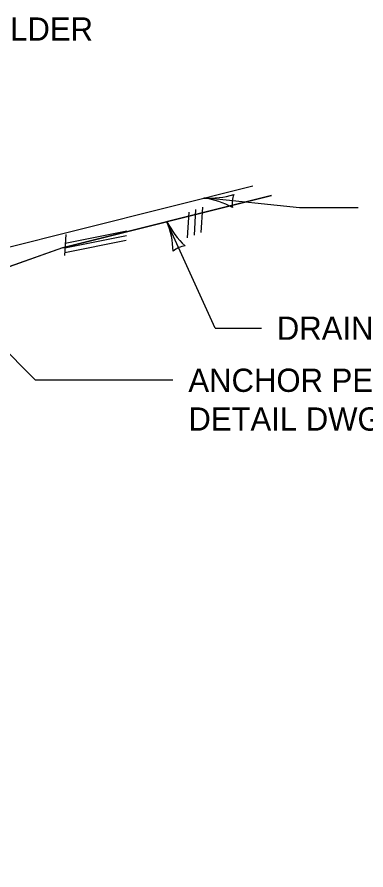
# Model space of a CAD drawing. Extents: x 49991.4 to 50021, y 49987.6 to 50011.4.
# Drawn here: x 50006.177 to 50007.078, y 49991.174 to 49993.376 of the extents above; entities that cross this region are included whole.
import ezdxf

# ---------------------------------------------------------------- set-up
doc = ezdxf.new("R2010")
doc.units = 0
for name, color, linetype in [('Level 1', 7, 'Continuous'), ('Level 2', 7, 'Continuous'), ('Level 3', 7, 'Continuous'), ('Level 4', 7, 'Continuous')]:
    doc.layers.add(name, color=color, linetype=linetype)

msp = doc.modelspace()

# ---------------------------------------------------------------- linework, layer by layer
at = {"layer": 'Level 1'}
for p, q in [((50006.1193, 49992.7741), (50006.7861, 49992.9408)), ((50006.6379, 49992.8791), (50006.6338, 49992.813)), ((50006.6554, 49992.8852), (50006.6513, 49992.82)), ((50006.6205, 49992.8726), (50006.6164, 49992.8065)), ((50006.3026, 49992.8153), (50006.2992, 49992.7609)), ((50006.3005, 49992.7807), (50006.4591, 49992.8126)), ((50006.3012, 49992.7927), (50006.46, 49992.8247)), ((50006.2997, 49992.7682), (50006.4584, 49992.8002))]:
    msp.add_line(p, q, dxfattribs=at)
msp.add_lwpolyline([(50006.8341, 49992.9155), (50006.2939, 49992.7804), (50006.1193, 49992.7186), (50006.0287, 49992.663), (50005.1465, 49992.663), (50002.1692, 49991.1744), (50001.4905, 49991.2052)], dxfattribs=at)
at = {"layer": 'Level 3'}
for p, q in [((50006.9067, 49992.8838), (50006.6595, 49992.9092)), ((50007.0578, 49992.8838), (50006.9067, 49992.8838)), ((50006.6882, 49992.573), (50006.564, 49992.8479)), ((50006.0677, 49992.5963), (50006.2243, 49992.4386)), ((50006.6882, 49992.573), (50006.8078, 49992.573)), ((50006.5793, 49992.4386), (50006.2243, 49992.4386))]:
    msp.add_line(p, q, dxfattribs=at)
for centre, radius, start, end in [((50006.6718, 49993.1418), 0.233, 266.9744, 286.2242), ((50006.787, 49992.8961), 0.0548, 156.2859, 192.0083), ((50006.6277, 49992.6891), 0.2223, 61.6031, 81.7866), ((50006.3577, 49992.7648), 0.2223, 1.7661, 21.9496), ((50006.7713, 49992.9542), 0.233, 207.1374, 226.3872), ((50006.6167, 49992.7311), 0.0548, 96.4489, 132.1713)]:
    msp.add_arc(centre, radius, start, end, dxfattribs=at)
at = {"layer": 'Level 4'}
for q in [(50006.8341, 49992.9155), (50006.1193, 49992.7186)]:
    msp.add_line((50006.2939, 49992.7804), q, dxfattribs=at)

# ---------------------------------------------------------------- texts
at = {"layer": 'Level 2'}
for s, p in [('SHOULDER', (50005.927, 49993.3154)), ('DRAINAGE BOTTOM', (50006.8478, 49992.543)), ('ANCHOR PER', (50006.6193, 49992.4086)), ('DETAIL DWG 208-12', (50006.6193, 49992.3086))]:
    msp.add_text(s, height=0.06, dxfattribs=at).set_placement(p)

doc.saveas('drawing.dxf')
